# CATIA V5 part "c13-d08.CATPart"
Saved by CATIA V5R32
Part number: Part1
Material "Alpine Fir": density 500 kg/m3, Young's modulus 1.7e+10 Pa, Poisson ratio 0.45, thermal expansion 3.75e-06 1/K
Bounding box of the stored display mesh (mm): x -163 to 95, y -77.362 to 77.362, z -85 to 85
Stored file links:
  D:\PROJECTS\Project 2022\CATIA V5 6R 2022\Resources\Part Files\c13_catia_v5_6r2022_prt\c13_catia_v5-6r2022_figr_13-31 & 32\c13-d08.CATPart
  C:\Program Files\Dassault Systemes\B32\win_b64\startup\materials\Catalog.CATMaterial
  C:\Program Files\Dassault Systemes\B32\win_b64\startup\materials\alpin_fir.jpg
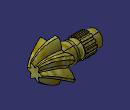
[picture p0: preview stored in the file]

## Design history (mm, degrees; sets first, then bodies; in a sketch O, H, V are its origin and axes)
Set1
  Plane1: type Offset, RefPlane face of Shaft1, Offset 45, reversed
  Plane2: type Offset, RefPlane Plane1, Offset 50, reversed
Body1 (main body), material "Alpine Fir"
  Sketch1 on zx-plane, origin (0, 0, 0), H (-1, 0, 0), V (0, 0, 1)
    axis line L1 (0, 0) -> (170, 0)
    line L2 (0, 0) -> (0, -45)
    point P2 (0, -45)
    line L3 (0, -45) -> (5, -45)
    point P3 (5, -45)
    line L4 (5, -45) -> (5, -39)
    line L5 (5, -39) -> (51, -39)
    line L6 (51, -39) -> (51, -38)
    point P6 (51, -38)
    line L7 (51, -38) -> (61, -38)
    point P7 (61, -38)
    line L8 (61, -38) -> (61, -36)
    point P8 (61, -36)
    arc A1 centre (72, -36) radius 11 from (61, -36) to (83, -36) cw
    point P10 (83, -36)
    line L9 (83, -36) -> (131, -36)
    line L10 (131, -36) -> (131, -32.5)
    line L11 (131, -32.5) -> (163, -32.5)
    line L12 (163, -32.5) -> (163, 0)
    point P14 (163, 0)
    line L13 (163, 0) -> (0, 0)
    radius about axis L11 L1 = 32.5
    radius about axis L9 L1 = 36
    radius about axis P7 L1 = 38
    radius about axis L5 L1 = 39
    radius about axis P3 L1 = 45
    length L11 = 32
    length L9 = 48
    distance P10 P8 = 22
    distance P7 P6 = 10
    length L5 = 46
    distance P3 P2 = 5
    horizontal: L1 H, L3 H, L5 H, L7 H, L9 H, L11 H, L13 H
    vertical: L2 V, L4 V, L6 V, L8 V, L12 V, L10 V
    tangency: A1 L8
    coincidence: P14 L1
  Shaft1: profile Sketch1, axis Sketch1.L1, angle 360
  Sketch2 on face of Shaft1, origin (-131, 0, 0), H (0, -1, 0), V (0, 0, 1)
    projected circle E1 centre (0, 0) radius 36 from edge [face of Shaft1 | face of Shaft1]
    projected arc E2 centre (0, 0) radius 36 from (5, 35.6511) to (-5, 35.6511) ccw from edge [face of Shaft1 | face of Shaft1]
    axis line L1 (0, 0) -> (0, 17.1744)
    point P2 (-5, 35.6511)
    line L2 (-5, 35.6511) -> (-5, 40.6511)
    point P3 (-5, 40.6511)
    line L3 (-5, 40.6511) -> (0, 40.6511)
    point P4 (0, 40.6511)
    point P5 (0, 40.6511)
    point P6 (5, 40.6511)
    line L4 (5, 40.6511) -> (0, 40.6511)
    point P7 (5, 35.6511)
    line L5 (5, 35.6511) -> (5, 40.6511)
    length L5 = 5
    distance L5 L2 = 10
    vertical: L1 V, L2 V
    coincidence: P2 E1, P4 L1, P4 P5
    horizontal: L3 H
    symmetry: P4 P5 L1, P3 P6 L1, L3 L4 L1, P2 P7 L1, L2 L5 L1
  Pad1: profile Sketch2, direction (1, 0, 0), length 48
  CircPattern1: of Pad1, instances 13, angular step 27.6923 {= 360.0*1 deg/CircPattern1.AngularNumber}, axis from face of Shaft1
  Loft1: solid, Sections (Sketch5; Sketch4; Sketch3)
  Sketch3 on Plane2, origin (95, 0, 0), H (0, -1, 0), V (0, 0, 1)
    construction line L1 through (0, 0) direction (1, 0)
    construction line L2 through (0, 0) direction (0, 1)
    arc A1 centre (23.3627, 6.7195) radius 24.375 from (13.5018, 29.0108) to (2.0971, 18.6324) ccw
    line L3 (18.3732, 26.1983) -> (13.5018, 29.0108)
    arc A2 centre (-5.8621, 23.5924) radius 24.375 from (15.0875, 11.1324) to (18.3732, 26.1983) ccw
    arc A3 centre (0, 0) radius 18.75 from (17.1847, 7.5) to (15.0875, 11.1324) ccw
    arc A4 centre (17.5006, -16.873) radius 24.375 from (31.875, 2.8125) to (17.1847, 7.5) ccw
    line L4 (31.875, -2.8125) -> (31.875, 2.8125)
    arc A5 centre (17.5006, 16.873) radius 24.375 from (17.1847, -7.5) to (31.875, -2.8125) ccw
    arc A6 centre (0, 0) radius 18.75 from (15.0875, -11.1324) to (17.1847, -7.5) ccw
    arc A7 centre (-5.8621, -23.5924) radius 24.375 from (18.3732, -26.1983) to (15.0875, -11.1324) ccw
    line L5 (13.5018, -29.0108) -> (18.3732, -26.1983)
    arc A8 centre (23.3627, -6.7195) radius 24.375 from (2.0971, -18.6324) to (13.5018, -29.0108) ccw
    arc A9 centre (0, 0) radius 18.75 from (-2.0971, -18.6324) to (2.0971, -18.6324) ccw
    arc A10 centre (-23.3627, -6.7195) radius 24.375 from (-13.5018, -29.0108) to (-2.0971, -18.6324) ccw
    line L6 (-18.3732, -26.1983) -> (-13.5018, -29.0108)
    arc A11 centre (5.8621, -23.5924) radius 24.375 from (-15.0875, -11.1324) to (-18.3732, -26.1983) ccw
    arc A12 centre (0, 0) radius 18.75 from (-17.1847, -7.5) to (-15.0875, -11.1324) ccw
    arc A13 centre (-17.5006, 16.873) radius 24.375 from (-31.875, -2.8125) to (-17.1847, -7.5) ccw
    line L7 (-31.875, 2.8125) -> (-31.875, -2.8125)
    arc A14 centre (-17.5006, -16.873) radius 24.375 from (-17.1847, 7.5) to (-31.875, 2.8125) ccw
    arc A15 centre (0, 0) radius 18.75 from (-15.0875, 11.1324) to (-17.1847, 7.5) ccw
    arc A16 centre (5.8621, 23.5924) radius 24.375 from (-18.3732, 26.1983) to (-15.0875, 11.1324) ccw
    line L8 (-13.5018, 29.0108) -> (-18.3732, 26.1983)
    arc A17 centre (-23.3627, 6.7195) radius 24.375 from (-2.0971, 18.6324) to (-13.5018, 29.0108) ccw
    arc A18 centre (0, 0) radius 18.75 from (2.0971, 18.6324) to (-2.0971, 18.6324) ccw
  Sketch4 on Plane1, origin (45, 0, 0), H (0, -1, 0), V (0, 0, 1)
    construction line L1 through (0, 0) direction (0.9659, -0.2588)
    construction line L2 through (0, 0) direction (0.2588, 0.9659)
    arc A1 centre (0, 0) radius 37.5 from (5.5935, -37.0805) to (13.6962, -34.9094) ccw
    arc A2 centre (-41.655, -25.0745) radius 48.75 from (-11.0664, -63.0336) to (5.5935, -37.0805) ccw
    arc A3 centre (48.6115, -0.8876) radius 48.75 from (13.6962, -34.9094) to (41.1006, -49.0555) ccw
    line L3 (49.0555, -41.1006) -> (41.1006, -49.0555)
    arc A4 centre (0.8876, -48.6115) radius 48.75 from (49.0555, -41.1006) to (34.9094, -13.6962) ccw
    arc A5 centre (0, 0) radius 37.5 from (34.9094, -13.6962) to (37.0805, -5.5935) ccw
    arc A6 centre (25.0745, 41.655) radius 48.75 from (37.0805, -5.5935) to (63.0336, 11.0664) ccw
    line L4 (60.1219, 21.933) -> (63.0336, 11.0664)
    arc A7 centre (42.5426, -23.5371) radius 48.75 from (60.1219, 21.933) to (29.3159, 23.3843) ccw
    arc A8 centre (0, 0) radius 37.5 from (29.3159, 23.3843) to (23.3843, 29.3159) ccw
    arc A9 centre (-23.5371, 42.5426) radius 48.75 from (23.3843, 29.3159) to (21.933, 60.1219) ccw
    line L5 (11.0664, 63.0336) -> (21.933, 60.1219)
    arc A10 centre (41.655, 25.0745) radius 48.75 from (11.0664, 63.0336) to (-5.5935, 37.0805) ccw
    arc A11 centre (0, 0) radius 37.5 from (-5.5935, 37.0805) to (-13.6962, 34.9094) ccw
    arc A12 centre (-48.6115, 0.8876) radius 48.75 from (-13.6962, 34.9094) to (-41.1006, 49.0555) ccw
    line L6 (-49.0555, 41.1006) -> (-41.1006, 49.0555)
    arc A13 centre (-0.8876, 48.6115) radius 48.75 from (-49.0555, 41.1006) to (-34.9094, 13.6962) ccw
    arc A14 centre (0, 0) radius 37.5 from (-34.9094, 13.6962) to (-37.0805, 5.5935) ccw
    arc A15 centre (-25.0745, -41.655) radius 48.75 from (-37.0805, 5.5935) to (-63.0336, -11.0664) ccw
    line L7 (-60.1219, -21.933) -> (-63.0336, -11.0664)
    arc A16 centre (-42.5426, 23.5371) radius 48.75 from (-60.1219, -21.933) to (-29.3159, -23.3843) ccw
    arc A17 centre (0, 0) radius 37.5 from (-29.3159, -23.3843) to (-23.3843, -29.3159) ccw
    arc A18 centre (23.5371, -42.5426) radius 48.75 from (-23.3843, -29.3159) to (-21.933, -60.1219) ccw
    line L8 (-11.0664, -63.0336) -> (-21.933, -60.1219)
  Sketch5 on face of Shaft1, origin (0, 0, 0), H (0, 1, 0), V (0, 0, 1)
    arc A1 centre (44.9945, 46.6682) radius 65 from (-20, 45.8258) to (-7.5, 85) cw
    point P1 (-7.5, 85)
    point P2 (7.5, 85)
    arc A2 centre (-44.9945, 46.6682) radius 65 from (20, 45.8258) to (7.5, 85) ccw
    line L1 (-7.5, 85) -> (7.5, 85)
    point P3 (7.5, 85)
    point P4 (20, 45.8258)
    point P5 (-20, 45.8258)
    point P6 (0, 0)
    arc A3 centre (0, 0) radius 50 from (29.6863, 40.2334) to (20, 45.8258) ccw
    arc A4 centre (-17.9186, 62.3005) radius 65 from (-49.6863, 5.5924) to (-77.3622, 36.0048) cw
    arc A5 centre (-62.9132, -15.6323) radius 65 from (-29.6863, 40.2334) to (-69.8622, 48.9952) ccw
    line L2 (-77.3622, 36.0048) -> (-69.8622, 48.9952)
    arc A6 centre (-62.9132, 15.6323) radius 65 from (-29.6863, -40.2334) to (-69.8622, -48.9952) cw
    arc A7 centre (-17.9186, -62.3005) radius 65 from (-49.6863, -5.5924) to (-77.3622, -36.0048) ccw
    line L3 (-69.8622, -48.9952) -> (-77.3622, -36.0048)
    arc A8 centre (-44.9945, -46.6682) radius 65 from (20, -45.8258) to (7.5, -85) cw
    arc A9 centre (44.9945, -46.6682) radius 65 from (-20, -45.8258) to (-7.5, -85) ccw
    line L4 (7.5, -85) -> (-7.5, -85)
    arc A10 centre (17.9186, -62.3005) radius 65 from (49.6863, -5.5924) to (77.3622, -36.0048) cw
    arc A11 centre (62.9132, 15.6323) radius 65 from (29.6863, -40.2334) to (69.8622, -48.9952) ccw
    line L5 (77.3622, -36.0048) -> (69.8622, -48.9952)
    arc A12 centre (62.9132, -15.6323) radius 65 from (29.6863, 40.2334) to (69.8622, 48.9952) cw
    arc A13 centre (17.9186, 62.3005) radius 65 from (49.6863, 5.5924) to (77.3622, 36.0048) ccw
    line L6 (69.8622, 48.9952) -> (77.3622, 36.0048)
    arc A14 centre (0, 0) radius 50 from (-49.6863, 5.5924) to (-49.6863, -5.5924) ccw
    arc A15 centre (0, 0) radius 50 from (-29.6863, -40.2334) to (-20, -45.8258) ccw
    arc A16 centre (0, 0) radius 50 from (20, -45.8258) to (29.6863, -40.2334) ccw
    arc A17 centre (0, 0) radius 50 from (49.6863, -5.5924) to (49.6863, 5.5924) ccw
    arc A18 centre (0, 0) radius 50 from (-20, 45.8258) to (-29.6863, 40.2334) ccw
    distance P4 P5 = 40
    radius A2 = 65
    length L1 = 15
    distance P6 L1 = 85
    radius A3 = 50
    symmetry: P1 P2 V, A1 A2 V, P4 P5 V
    coincidence: P3 A2, P6 O, P5 A3, A3 A14, A14 A15, A15 A16, A16 A17, A3 A18
    horizontal: L1 H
